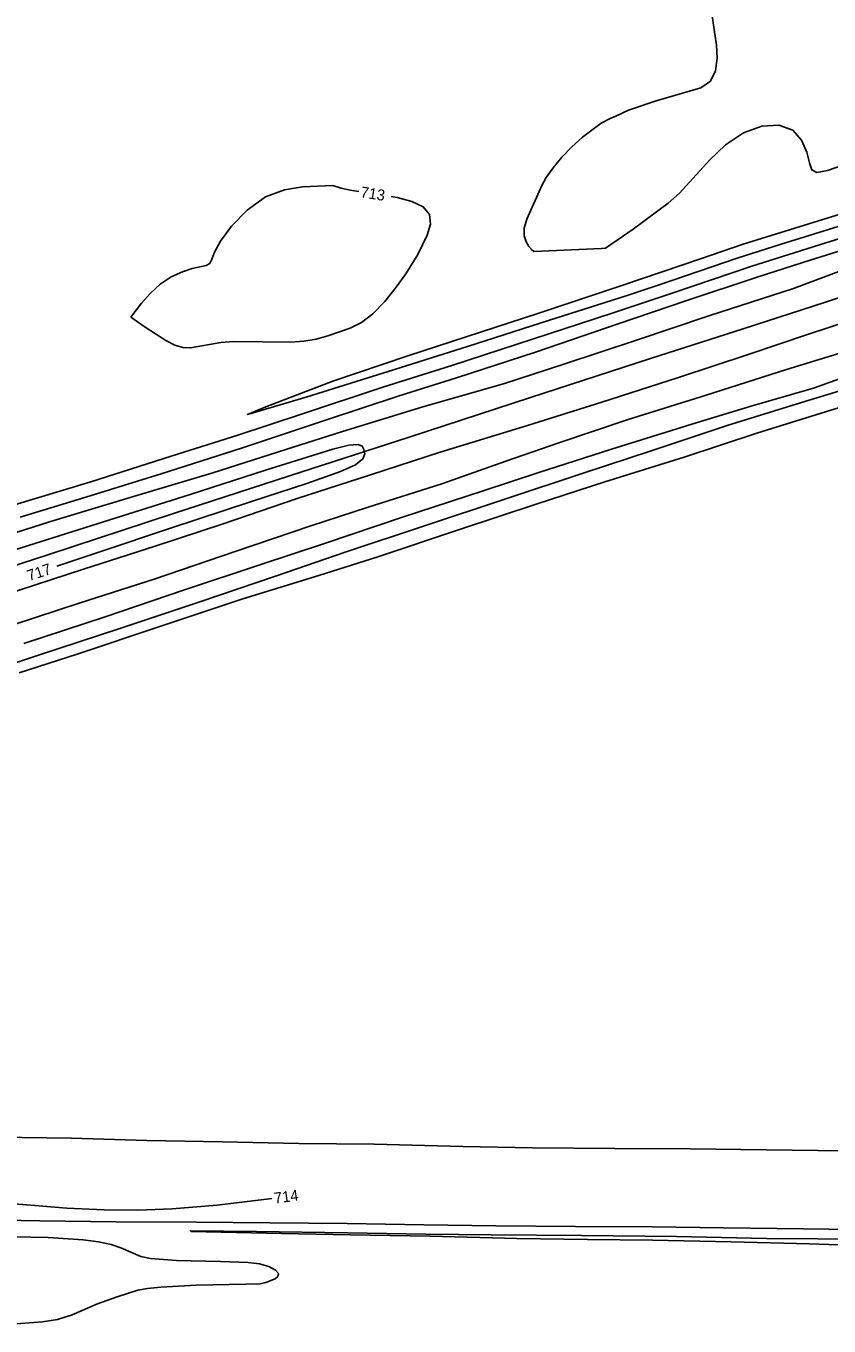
# Model space of a CAD drawing. Extents: x -468548933 to 3387700, y -306089263 to 1207014.
# Drawn here: x 1838588.1 to 1838881.6, y 536181.2 to 536656.4 of the extents above; entities that cross this region are included whole.
import ezdxf

# ---------------------------------------------------------------- set-up
doc = ezdxf.new("R2010")
doc.units = 0
for name, color, linetype in [('DT_X_Contour_Minor', 7, 'Continuous'), ('Level 14', 7, 'Continuous'), ('Level 19', 7, 'Continuous')]:
    doc.layers.add(name, color=color, linetype=linetype)

msp = doc.modelspace()

# ---------------------------------------------------------------- linework, layer by layer
at = {"layer": 'DT_X_Contour_Minor'}
for points in [[(1838887.77, 536605.9), (1838881.04, 536603.58), (1838877.16, 536602.85), (1838875.4, 536603.78), (1838874.55, 536606.35), (1838873.52, 536610.32), (1838871.64, 536614.71), (1838868.36, 536618.31), (1838863.34, 536620.09), (1838857.1, 536619.81), (1838850.37, 536617.36), (1838843.86, 536612.91), (1838838.05, 536607.49), (1838826.97, 536595.26), (1838822.82, 536591.63), (1838810.09, 536582.17), (1838799.91, 536575.15), (1838798.44, 536575.02), (1838773.67, 536574.02), (1838772.85, 536574.69), (1838771.94, 536575.81), (1838770.94, 536577.46), (1838770.2, 536579.67), (1838770.17, 536582.47), (1838771.11, 536585.81), (1838776.63, 536598.14), (1838778.28, 536601.05), (1838780.76, 536604.54), (1838783.96, 536608.38), (1838787.65, 536612.24), (1838791.56, 536615.79), (1838798.29, 536620.88), (1838801.64, 536622.57), (1838803.7, 536623.48), (1838808.38, 536625.62), (1838818.5, 536628.98), (1838834.81, 536633.74), (1838838.29, 536636.25), (1838840.17, 536640.01), (1838840.75, 536644.61), (1838840.47, 536649.43), (1838838.01, 536666.64)], [(1838688.74, 536514.52), (1838718.58, 536524.39), (1838743.72, 536532.32), (1838773.24, 536541.87), (1838802.31, 536551.47), (1838824.64, 536558.91), (1838853.42, 536568.62), (1838878.19, 536576.43), (1838907.11, 536585.41), (1838939.11, 536595.34), (1838967.33, 536604.29), (1838994.62, 536613.53), (1839021.67, 536622.69), (1839048.26, 536631.35), (1839076.86, 536640.64), (1839088.54, 536644.59)], [(1838626.34, 536550), (1838630.29, 536555.07), (1838633.41, 536558.6), (1838637.14, 536562.02), (1838641.19, 536564.68), (1838645.22, 536566.55), (1838648.85, 536567.71), (1838653.93, 536568.83), (1838655.3, 536569.61), (1838656.04, 536571.1), (1838656.99, 536573.68), (1838659.15, 536577.7), (1838663.23, 536583.21), (1838668.91, 536589.09), (1838675.59, 536593.89), (1838682.61, 536596.55), (1838689.13, 536597.58), (1838700.23, 536598.14), (1838703.34, 536597.11), (1838706.63, 536596.37), (1838709.71, 536595.89)], [(1838721.57, 536594.05), (1838723.78, 536593.71), (1838729.17, 536592.27), (1838733.27, 536590.27), (1838735.59, 536587.51), (1838735.89, 536583.92), (1838734.77, 536579.93), (1838731.34, 536572.82), (1838726.88, 536565.75), (1838723.41, 536560.88), (1838719.28, 536555.7), (1838714.92, 536551.17), (1838710.67, 536548.03), (1838706.53, 536545.97), (1838698.36, 536543.1), (1838694.14, 536541.92), (1838689.68, 536541.14), (1838684.9, 536540.88), (1838664.06, 536541.12), (1838659.27, 536540.69), (1838648.26, 536538.73), (1838645.35, 536538.89), (1838642.43, 536539.78), (1838639.16, 536541.42), (1838631.61, 536546.3), (1838626.34, 536550)], [(1838908.12, 536594.54), (1838879.33, 536585.63), (1838850.32, 536576.59), (1838834.69, 536571.29), (1838806.23, 536561.61), (1838775.58, 536551.39), (1838749.04, 536542.74), (1838727.72, 536535.78), (1838700.2, 536526.6), (1838675.8, 536517.18), (1838669.04, 536514.39), (1838690.82, 536520.88), (1838720.42, 536530.04), (1838749.48, 536539.19), (1838779.5, 536548.92), (1838807.54, 536557.81), (1838819.96, 536561.91), (1838848.06, 536571.56), (1838864.14, 536576.63), (1838897.2, 536586.91)], [(1838585.94, 536476.91), (1838609.95, 536484.19), (1838637.49, 536492.73), (1838666.83, 536502.12), (1838697.52, 536512.33), (1838724.49, 536521.16), (1838745.42, 536527.84), (1838774.38, 536537.21), (1838804.55, 536547.5), (1838829.32, 536555.9), (1838855.37, 536564.57), (1838875.1, 536570.9), (1838905.77, 536580.41)], [(1838566.41, 536465.51), (1838596.66, 536475.21), (1838626.14, 536484.02), (1838656.42, 536493.1), (1838683.07, 536501.62), (1838703.8, 536508.22), (1838733.09, 536517.16), (1838762.69, 536525.55), (1838784.72, 536532.75), (1838811.21, 536541.58), (1838837.69, 536550.5), (1838868.66, 536560.47), (1838887.23, 536567.43)], [(1838902.11, 536552.91), (1838874.15, 536543.74), (1838852.09, 536536.33), (1838826.57, 536527.94), (1838798.59, 536518.94), (1838771.44, 536510.34), (1838739.49, 536500.64), (1838714.01, 536492.38), (1838687.15, 536483.63), (1838660.12, 536474.47), (1838635.24, 536466.24), (1838609.1, 536457.8), (1838579.97, 536448.33)], [(1838894.39, 536539.53), (1838866.05, 536530.84), (1838836.75, 536521.42), (1838808.24, 536512.57), (1838782.85, 536504.05), (1838763.55, 536497.34), (1838740.05, 536489.08), (1838713.1, 536480.53), (1838692.2, 536473.63), (1838664.55, 536464.32), (1838634.96, 536454.17), (1838607.89, 536445.55), (1838583.38, 536437.48)], [(1838902.05, 536528.06), (1838871.53, 536518.76), (1838844.37, 536510.38), (1838816.65, 536501.13), (1838792.1, 536493.07), (1838763.52, 536483.61), (1838733.41, 536473.56), (1838705.11, 536464.13), (1838679.25, 536455.26), (1838651.99, 536446.04), (1838621.97, 536436.05), (1838592.63, 536426.36), (1838568.47, 536418.35)], [(1838886.81, 536527.91), (1838875.94, 536524.06), (1838853.54, 536517.54), (1838833.1, 536511.39), (1838802.1, 536501.66), (1838775.59, 536493.15), (1838755.19, 536486.49), (1838725.39, 536476.69), (1838697.51, 536467.41), (1838673.55, 536459.49), (1838646.05, 536450.3), (1838617.06, 536440.47), (1838587.29, 536430.67)], [(1838585.52, 536419.95), (1838606.75, 536426.84), (1838636.6, 536436.75), (1838667.39, 536447.06), (1838695.1, 536455.48), (1838716.66, 536462.41), (1838746.61, 536472.35), (1838774.89, 536481.73), (1838799.7, 536489.72), (1838828.72, 536498.81), (1838855.3, 536507.54), (1838880.39, 536515.41), (1838902.03, 536522.1)], [(1838582.69, 536480.96), (1838611.75, 536489.81), (1838641.16, 536499.1), (1838665.48, 536506.8), (1838688.74, 536514.52)], [(1838557.1, 536456.36), (1838588.57, 536466.34), (1838614.06, 536474.38), (1838648.05, 536485.12), (1838675.67, 536493.99), (1838700.27, 536501.69), (1838706.1, 536503.14), (1838709.51, 536503.45), (1838711.02, 536502.81), (1838711.61, 536501.56), (1838711.93, 536500.01), (1838711.24, 536498.16), (1838708.47, 536495.98), (1838703.03, 536493.5), (1838690.72, 536489.17), (1838670.48, 536482.53), (1838640.47, 536472.68), (1838615.41, 536464.3), (1838599.28, 536458.9)], [(1838577.43, 536250.22), (1838604.68, 536249.9), (1838632.19, 536249), (1838659.95, 536248.56), (1838687.78, 536247.88), (1838715.38, 536247.65), (1838747.77, 536246.81), (1838773.25, 536246.36), (1838803.35, 536246.12), (1838831.01, 536246.03), (1838858.67, 536245.59), (1838887.16, 536245.2)], [(1838677.99, 536227.8), (1838676.01, 536227.54), (1838657.93, 536225.39), (1838641.56, 536224.02), (1838628.96, 536223.5), (1838616.6, 536223.63), (1838603.01, 536224.29), (1838576.39, 536226.45)], [(1838899.98, 536216.34), (1838872.28, 536216.69), (1838843.04, 536217.07), (1838817.1, 536217.41), (1838788.91, 536217.56), (1838759.79, 536217.79), (1838733.56, 536218.18), (1838705.46, 536218.72), (1838677.25, 536218.89), (1838650.38, 536219.14), (1838620.89, 536219.29), (1838593.11, 536219.65), (1838565.56, 536220.12)], [(1838892.21, 536210.65), (1838874.47, 536211.23), (1838845.86, 536211.93), (1838817.08, 536212.56), (1838793.33, 536212.79), (1838767.55, 536213.21), (1838735.83, 536214.04), (1838706.57, 536214.55), (1838681.53, 536214.99), (1838648.42, 536215.82), (1838648.19, 536216.04), (1838672.35, 536215.71), (1838705.61, 536215.26), (1838734.24, 536214.83)], [(1838734.24, 536214.83), (1838758.09, 536214.6), (1838791.19, 536214.32), (1838825.87, 536213.96), (1838858.85, 536213.22), (1838877.56, 536213.13), (1838907.39, 536212.97)], [(1838570.88, 536214), (1838596.19, 536213.52), (1838608.91, 536212.73), (1838614.57, 536211.95), (1838619.21, 536210.95), (1838622.75, 536209.82), (1838630, 536206.59), (1838633.59, 536205.91), (1838643.12, 536205.14), (1838659.22, 536204.76), (1838669.23, 536204.48), (1838673.46, 536203.92), (1838676.86, 536202.92), (1838679.24, 536201.65), (1838680.38, 536200.39), (1838680.19, 536199.34), (1838679.14, 536198.52), (1838675.73, 536197.07), (1838673.63, 536196.65), (1838668.44, 536196.46), (1838650.22, 536196.19), (1838637.37, 536195.46), (1838632.45, 536194.92), (1838629, 536194.27), (1838621.44, 536191.88), (1838614.26, 536189.29), (1838604.89, 536185.3), (1838599.58, 536183.64), (1838594.05, 536182.72), (1838573.12, 536181.22)]]:
    msp.add_lwpolyline(points, dxfattribs=at)
at = {"layer": 'Level 14'}
msp.add_lwpolyline([(1838067.23, 536291.44), (1838108.15, 536304.5), (1838151.08, 536318.56), (1838193.63, 536332.5), (1838234.22, 536345.7), (1838275.4, 536358.98), (1838314.79, 536371.83), (1838356.22, 536385.31), (1838394.77, 536397.81), (1838433.7, 536410.35), (1838471.79, 536422.71), (1838509.52, 536434.92), (1838553.19, 536449.23), (1838596.01, 536463.11), (1838642.04, 536478.18), (1838684.42, 536491.95), (1838728.12, 536506.11), (1838772.46, 536520.55), (1838816.43, 536534.82), (1838850.28, 536545.75), (1838880.4, 536555.5), (1838950.35, 536578.67)], dxfattribs=at)

# ---------------------------------------------------------------- texts
at = {"layer": 'Level 19'}
for s, rotation, p in [('713', 351.1888, (1838710.16, 536593.8)), ('717', 18.4836, (1838589.23, 536453.44)), ('714', 7.6604, (1838679.04, 536225.93))]:
    msp.add_text(s, height=4, rotation=rotation, dxfattribs=at).set_placement(p)

doc.saveas('drawing.dxf')
